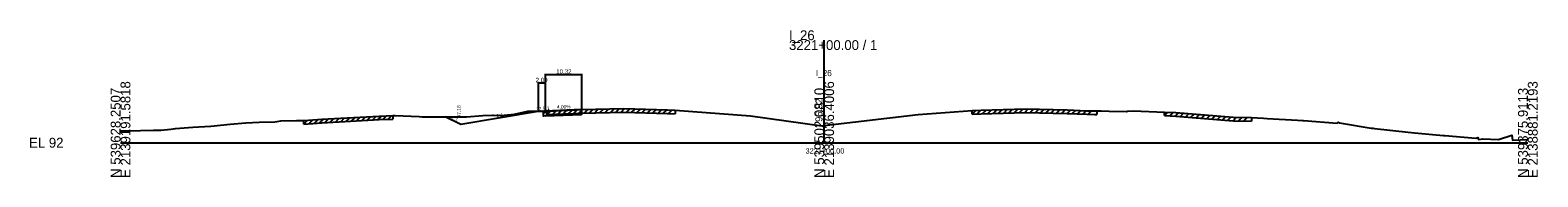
# Model space of a CAD drawing. Extents: x -13101 to 4803, y -924 to 22390.
# Drawn here: x 1974.3 to 2402.8, y 10490.3 to 10532 of the extents above; entities that cross this region are included whole.
import ezdxf

# ---------------------------------------------------------------- set-up
doc = ezdxf.new("R2010")
doc.units = 0
for name, color, linetype in [('RD_GPK_XS_Cell', 7, 'Continuous'), ('RD_XD_TX_Width', 7, 'Continuous'), ('RD_XS_Base', 7, 'Continuous'), ('RD_XS_EarthShd', 7, 'Continuous'), ('RD_XS_EwShp', 7, 'Continuous'), ('RD_XS_ExGround', 7, 'Continuous'), ('RD_XS_ExPaveRet', 7, 'Continuous'), ('RD_XS_OSBase', 7, 'Continuous'), ('RD_XS_Pave', 7, 'Continuous'), ('RD_XS_TieSlope', 7, 'Continuous'), ('RD_XS_TX_Baseline', 7, 'Continuous'), ('RD_XS_TX_Elev_EX', 7, 'Continuous'), ('RD_XS_TX_Elev_PR', 7, 'Continuous'), ('RD_XS_TX_ShdSlope', 7, 'Continuous'), ('RD_XS_TX_Slope', 7, 'Continuous'), ('RD_XS_TX_Station', 7, 'Continuous')]:
    doc.layers.add(name, color=color, linetype=linetype)

msp = doc.modelspace()

# ---------------------------------------------------------------- linework, layer by layer
at = {"layer": 'RD_GPK_XS_Cell'}
for p, q in [((2200, 10500), (2200, 10529.15)), ((2000, 10500), (2200, 10500)), ((2200, 10500), (2400, 10500))]:
    msp.add_line(p, q, dxfattribs=at)
at = {"layer": 'RD_XD_TX_Width'}
for p, q in [((2118.68, 10517.15), (2118.68, 10509.04)), ((2120.68, 10516.95), (2118.68, 10516.95)), ((2120.68, 10519.57), (2120.68, 10509.2)), ((2120.68, 10519.37), (2131, 10519.37)), ((2120.68, 10517.15), (2120.68, 10509.2)), ((2131, 10519.57), (2131, 10509.62))]:
    msp.add_line(p, q, dxfattribs=at)
at = {"layer": 'RD_XS_Base'}
msp.add_line((2120.68, 10507.6), (2131, 10508.02), dxfattribs=at)
at = {"layer": 'RD_XS_EarthShd'}
msp.add_line((2120.68, 10509), (2118.68, 10508.84), dxfattribs=at)
at = {"layer": 'RD_XS_EwShp'}
for points in [[(2120.56, 10508.99), (2118.68, 10508.84), (2096.68, 10505.18), (2092.31, 10507.36), (2095.71, 10507.34), (2096.22, 10507.34), (2097.99, 10507.32), (2098.31, 10507.36), (2102.94, 10507.77), (2105.72, 10507.86), (2106.05, 10507.86), (2107.96, 10507.77), (2111.95, 10508.1), (2115.73, 10509.01), (2117.35, 10509)], [(2120.68, 10508.99), (2121.27, 10508.98), (2131, 10509.42), (2131, 10509.02), (2131, 10508.02), (2120.68, 10507.6), (2120.18, 10507.58), (2120.18, 10508.58), (2120.68, 10508.6)], [(2120.56, 10508.99), (2120.59, 10508.99), (2120.68, 10508.99), (2120.68, 10509)]]:
    msp.add_lwpolyline(points, close=True, dxfattribs=at)
at = {"layer": 'RD_XS_ExGround'}
msp.add_lwpolyline([(2000, 10503.39), (2005.63, 10503.45), (2009.37, 10503.55), (2011.48, 10503.58), (2014.27, 10503.89), (2015.64, 10504.07), (2020.57, 10504.41), (2025.65, 10504.72), (2031.13, 10505.25), (2035.65, 10505.69), (2039.39, 10505.83), (2043.81, 10505.91), (2045.6, 10506.21), (2049.99, 10506.35), (2052.08, 10506.32), (2057.18, 10506.68), (2073.54, 10507.57), (2077.38, 10507.73), (2078.04, 10507.71), (2084.86, 10507.46), (2085.7, 10507.4), (2087.78, 10507.39), (2095.71, 10507.34), (2096.22, 10507.34), (2097.99, 10507.32), (2098.31, 10507.36), (2102.94, 10507.77), (2105.72, 10507.86), (2106.05, 10507.86), (2107.96, 10507.77), (2111.95, 10508.1), (2115.73, 10509.01), (2117.35, 10509), (2120.59, 10508.99), (2121.27, 10508.98), (2131.09, 10509.42), (2143.02, 10509.72), (2155.45, 10509.34), (2157.66, 10509.25), (2179.05, 10507.6), (2199.29, 10504.83), (2200, 10504.92), (2226.68, 10508.07), (2242.02, 10509.14), (2244.51, 10509.24), (2257.26, 10509.63), (2269.09, 10509.34), (2274.62, 10509.11), (2276.93, 10509.06), (2277.47, 10509.07), (2278.76, 10509.05), (2281.03, 10509.01), (2285.89, 10508.91), (2286.23, 10508.98), (2287.91, 10509.07), (2296.75, 10508.73), (2299.93, 10508.57), (2316.22, 10507.27), (2321.43, 10507.13), (2324.82, 10506.94), (2325.93, 10506.9), (2334.53, 10506.43), (2335.94, 10506.32), (2336.25, 10506.32), (2345.83, 10505.55), (2346.11, 10505.89), (2346.5, 10505.7), (2355.47, 10504.17), (2355.96, 10504.1), (2356.4, 10504.05), (2365.97, 10503), (2367.77, 10502.84), (2375.98, 10502.09), (2376.37, 10502.08), (2385.17, 10501.3), (2385.77, 10501.5), (2385.99, 10500.93), (2387.25, 10501.14), (2391.7, 10500.93), (2395.44, 10502.17), (2395.63, 10500.75), (2400, 10500.9)], dxfattribs=at)
at = {"layer": 'RD_XS_ExPaveRet'}
for p, q in [((2074.58, 10506.61), (2075.62, 10507.65)), ((2076.08, 10506.67), (2077.12, 10507.72)), ((2077.38, 10507.73), (2077.38, 10506.73)), ((2121.27, 10507.98), (2122.32, 10509.03)), ((2121.27, 10507.98), (2121.27, 10508.98)), ((2121.27, 10507.98), (2131.09, 10508.42)), ((2122.77, 10508.05), (2123.82, 10509.09)), ((2124.27, 10508.11), (2125.32, 10509.16)), ((2125.77, 10508.18), (2126.82, 10509.23)), ((2127.27, 10508.25), (2128.32, 10509.3)), ((2128.77, 10508.32), (2129.82, 10509.36)), ((2130.27, 10508.38), (2131.31, 10509.43)), ((2131.09, 10508.42), (2143.02, 10508.72)), ((2131.77, 10508.44), (2132.8, 10509.46)), ((2133.27, 10508.47), (2134.3, 10509.5)), ((2134.77, 10508.51), (2135.8, 10509.54)), ((2136.27, 10508.55), (2137.3, 10509.57)), ((2137.77, 10508.59), (2138.8, 10509.61)), ((2139.27, 10508.62), (2140.3, 10509.65)), ((2140.77, 10508.66), (2141.8, 10509.69)), ((2142.27, 10508.7), (2143.28, 10509.71)), ((2143.02, 10508.72), (2155.45, 10508.34)), ((2143.77, 10508.69), (2144.74, 10509.66)), ((2145.27, 10508.65), (2146.24, 10509.62)), ((2146.77, 10508.6), (2147.74, 10509.57)), ((2148.27, 10508.56), (2149.24, 10509.53)), ((2149.77, 10508.51), (2150.74, 10509.48)), ((2151.27, 10508.47), (2152.24, 10509.44)), ((2152.77, 10508.42), (2153.74, 10509.39)), ((2154.27, 10508.38), (2155.24, 10509.35)), ((2155.45, 10508.34), (2157.66, 10508.25)), ((2155.77, 10508.33), (2156.73, 10509.29)), ((2157.66, 10509.25), (2157.66, 10508.25)), ((2242.02, 10508.14), (2243.06, 10509.18)), ((2242.02, 10508.14), (2242.02, 10509.14)), ((2242.02, 10508.14), (2244.51, 10508.24)), ((2243.52, 10508.2), (2244.56, 10509.24)), ((2244.51, 10508.24), (2257.26, 10508.63)), ((2245.02, 10508.26), (2246.05, 10509.29)), ((2246.52, 10508.3), (2247.55, 10509.33)), ((2248.02, 10508.35), (2249.05, 10509.38)), ((2249.52, 10508.39), (2250.55, 10509.42)), ((2251.02, 10508.44), (2252.05, 10509.47)), ((2252.52, 10508.48), (2253.55, 10509.51)), ((2254.02, 10508.53), (2255.05, 10509.56)), ((2255.52, 10508.57), (2256.55, 10509.6)), ((2257.02, 10508.62), (2258, 10509.61)), ((2257.26, 10508.63), (2269.09, 10508.34)), ((2258.52, 10508.6), (2259.49, 10509.57)), ((2260.02, 10508.56), (2260.99, 10509.54)), ((2261.52, 10508.52), (2262.49, 10509.5)), ((2263.02, 10508.49), (2263.99, 10509.46)), ((2264.52, 10508.45), (2265.49, 10509.43)), ((2266.02, 10508.41), (2266.99, 10509.39)), ((2267.52, 10508.38), (2268.49, 10509.35)), ((2269.02, 10508.34), (2269.98, 10509.3)), ((2269.09, 10508.34), (2274.62, 10508.11)), ((2270.52, 10508.28), (2271.48, 10509.24)), ((2272.02, 10508.22), (2272.98, 10509.18)), ((2273.52, 10508.15), (2274.48, 10509.11)), ((2274.62, 10508.11), (2276.93, 10508.06)), ((2275.02, 10508.1), (2276, 10509.08)), ((2276.93, 10508.06), (2277.47, 10508.07)), ((2277.47, 10509.07), (2277.47, 10508.07)), ((2296.75, 10507.73), (2296.75, 10508.73)), ((2296.75, 10507.73), (2297.7, 10508.68)), ((2296.75, 10507.73), (2299.93, 10507.57)), ((2298.25, 10507.65), (2299.2, 10508.61)), ((2299.75, 10507.58), (2300.68, 10508.51)), ((2301.25, 10507.47), (2302.17, 10508.39)), ((2302.75, 10507.35), (2303.67, 10508.27)), ((2304.25, 10507.23), (2305.17, 10508.15)), ((2305.75, 10507.11), (2306.67, 10508.04)), ((2307.25, 10506.99), (2308.17, 10507.92)), ((2308.75, 10506.87), (2309.67, 10507.8)), ((2310.25, 10506.75), (2311.17, 10507.68)), ((2052.08, 10505.32), (2053.15, 10506.4)), ((2052.08, 10505.32), (2052.08, 10506.32)), ((2052.08, 10505.32), (2057.18, 10505.68)), ((2053.58, 10505.43), (2054.65, 10506.5)), ((2055.08, 10505.53), (2056.15, 10506.6)), ((2056.58, 10505.63), (2057.65, 10506.7)), ((2057.18, 10505.68), (2073.54, 10506.57)), ((2058.08, 10505.72), (2059.14, 10506.78)), ((2059.58, 10505.81), (2060.64, 10506.86)), ((2061.08, 10505.89), (2062.14, 10506.95)), ((2062.58, 10505.97), (2063.64, 10507.03)), ((2064.08, 10506.05), (2065.14, 10507.11)), ((2065.58, 10506.13), (2066.64, 10507.19)), ((2067.08, 10506.22), (2068.14, 10507.27)), ((2068.58, 10506.3), (2069.64, 10507.36)), ((2070.08, 10506.38), (2071.14, 10507.44)), ((2071.58, 10506.46), (2072.64, 10507.52)), ((2073.08, 10506.55), (2074.13, 10507.59)), ((2073.54, 10506.57), (2077.38, 10506.73)), ((2299.93, 10507.57), (2316.22, 10506.27)), ((2311.75, 10506.63), (2312.67, 10507.56)), ((2313.25, 10506.51), (2314.17, 10507.44)), ((2314.75, 10506.39), (2315.67, 10507.32)), ((2316.22, 10506.27), (2321.43, 10506.13)), ((2316.25, 10506.27), (2317.22, 10507.24)), ((2317.75, 10506.23), (2318.72, 10507.2)), ((2319.25, 10506.19), (2320.22, 10507.16)), ((2321.43, 10507.13), (2321.43, 10506.13))]:
    msp.add_line(p, q, dxfattribs=at)
at = {"layer": 'RD_XS_OSBase'}
for p, q in [((2120.18, 10508.58), (2120.68, 10508.6)), ((2120.18, 10507.58), (2120.18, 10508.58)), ((2120.68, 10508.6), (2120.68, 10509)), ((2131, 10509.02), (2131, 10509.42)), ((2131, 10508.02), (2131, 10509.02)), ((2120.68, 10507.6), (2120.18, 10507.58))]:
    msp.add_line(p, q, dxfattribs=at)
at = {"layer": 'RD_XS_Pave'}
msp.add_line((2131, 10509.42), (2120.68, 10509), dxfattribs=at)
at = {"layer": 'RD_XS_TieSlope'}
for p, q in [((2118.68, 10508.84), (2096.68, 10505.18)), ((2096.68, 10505.18), (2092.31, 10507.36))]:
    msp.add_line(p, q, dxfattribs=at)

# ---------------------------------------------------------------- texts
at = {"layer": 'RD_GPK_XS_Cell'}
for s, p in [('3221+00.00 / 1', (2190, 10526.35)), ('I_26', (2190, 10529.15)), ('EL 92', (1974, 10498.6))]:
    msp.add_text(s, height=2.8, dxfattribs=at).set_placement(p)
for s, p in [('E 2139191.5818', (2002.8, 10490)), ('E 2139036.4006', (2202.8, 10490)), ('E 2138881.2193', (2402.8, 10490)), ('N 539628.2507', (2000, 10490)), ('N 539502.0810', (2200, 10490)), ('N 539375.9113', (2400, 10490))]:
    msp.add_text(s, height=2.8, rotation=90, dxfattribs=at).set_placement(p)
at = {"layer": 'RD_XD_TX_Width'}
for s, p in [('10.32', (2123.85, 10519.62)), ('2.00', (2117.99, 10517.2))]:
    msp.add_text(s, height=1.25, dxfattribs=at).set_placement(p)
at = {"layer": 'RD_XS_TX_Baseline'}
msp.add_text('I_26', height=1.75, dxfattribs=at).set_placement((2197.6, 10518.92))
at = {"layer": 'RD_XS_TX_Elev_EX'}
msp.add_text('96.92', height=2, rotation=90, dxfattribs=at).set_placement((2199.5, 10505.92))
at = {"layer": 'RD_XS_TX_Elev_PR'}
msp.add_text('97.18', height=1, rotation=90, dxfattribs=at).set_placement((2096.68, 10507.18))
at = {"layer": 'RD_XS_TX_ShdSlope'}
msp.add_text('12.5:1', height=1, rotation=4.5739, dxfattribs=at).set_placement((2118.14, 10509.05))
msp.add_text('12.5:1', height=1, rotation=4.5739, dxfattribs=at).set_placement((2118.14, 10509.05))
at = {"layer": 'RD_XS_TX_Slope'}
for s, rotation, p in [('2:1', 333.4349, (2093.93, 10506.83)), ('6:1', 9.4623, (2106.94, 10507.14)), ('4.00%', 2.2906, (2124.02, 10509.64))]:
    msp.add_text(s, height=1, rotation=rotation, dxfattribs=at).set_placement(p)
at = {"layer": 'RD_XS_TX_Station'}
msp.add_text('3221+00.00', height=1.5, dxfattribs=at).set_placement((2194.71, 10496.92))

doc.saveas('drawing.dxf')
